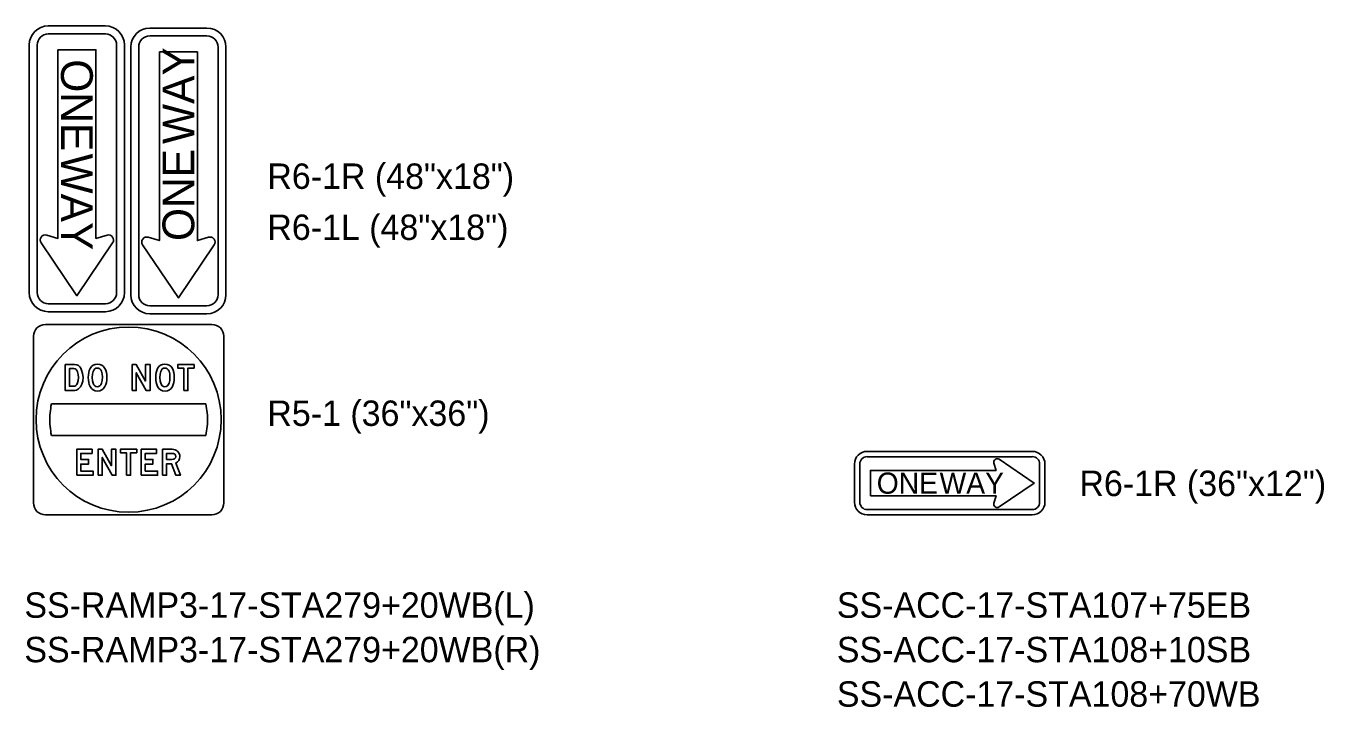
# Model space of a CAD drawing. Extents: x 620856.8 to 620948.6, y 415598.8 to 415658.2.
# Drawn here: x 620925.25 to 620945.7, y 415616.01 to 415626.74 of the extents above; entities that cross this region are included whole.
import ezdxf

# ---------------------------------------------------------------- set-up
doc = ezdxf.new("R2010")
doc.units = 0
doc.layers.add('SIGNS', color=7, linetype='Continuous')

msp = doc.modelspace()

# ---------------------------------------------------------------- linework, layer by layer
at = {"layer": 'SIGNS'}
for p, q in [((620925.604, 415626.741), (620926.504, 415626.741)), ((620927.203, 415626.708), (620928.103, 415626.708)), ((620925.304, 415622.541), (620925.304, 415626.441)), ((620926.903, 415622.508), (620926.903, 415626.408)), ((620926.504, 415622.241), (620925.604, 415622.241)), ((620928.103, 415622.208), (620927.203, 415622.208)), ((620928.182, 415622.041), (620925.557, 415622.041)), ((620928.182, 415622.041), (620925.557, 415622.041)), ((620925.369, 415621.853), (620925.369, 415619.228)), ((620925.369, 415621.853), (620925.369, 415619.228)), ((620928.369, 415619.228), (620928.369, 415621.853)), ((620928.369, 415619.228), (620928.369, 415621.853)), ((620925.641, 415620.718), (620925.636, 415620.683)), ((620925.646, 415620.754), (620925.641, 415620.718)), ((620925.653, 415620.789), (620925.646, 415620.754)), ((620928.085, 415620.789), (620925.653, 415620.789)), ((620928.092, 415620.754), (620928.085, 415620.789)), ((620928.098, 415620.718), (620928.092, 415620.754)), ((620928.103, 415620.683), (620928.098, 415620.718)), ((620925.629, 415620.576), (620925.628, 415620.541)), ((620925.628, 415620.541), (620925.629, 415620.505)), ((620925.63, 415620.612), (620925.629, 415620.576)), ((620925.632, 415620.647), (620925.63, 415620.612)), ((620925.636, 415620.683), (620925.632, 415620.647)), ((620928.106, 415620.647), (620928.103, 415620.683)), ((620928.109, 415620.612), (620928.106, 415620.647)), ((620928.11, 415620.576), (620928.109, 415620.612)), ((620928.11, 415620.54), (620928.11, 415620.576)), ((620928.11, 415620.505), (620928.11, 415620.54)), ((620925.629, 415620.505), (620925.63, 415620.469)), ((620925.63, 415620.469), (620925.632, 415620.434)), ((620925.632, 415620.434), (620925.636, 415620.398)), ((620925.636, 415620.398), (620925.641, 415620.363)), ((620925.641, 415620.363), (620925.646, 415620.327)), ((620925.646, 415620.327), (620925.653, 415620.293)), ((620928.085, 415620.293), (620928.092, 415620.327)), ((620928.092, 415620.327), (620928.098, 415620.363)), ((620928.098, 415620.363), (620928.103, 415620.398)), ((620928.103, 415620.398), (620928.106, 415620.434)), ((620928.106, 415620.434), (620928.109, 415620.469)), ((620928.109, 415620.469), (620928.11, 415620.505)), ((620925.653, 415620.293), (620928.085, 415620.293)), ((620938.304, 415619.241), (620938.304, 415619.841)), ((620941.304, 415619.841), (620941.304, 415619.241)), ((620925.557, 415619.041), (620928.182, 415619.041)), ((620925.557, 415619.041), (620928.182, 415619.041)), ((620941.104, 415619.041), (620938.504, 415619.041))]:
    msp.add_line(p, q, dxfattribs=at)
for points in [[(620926.504, 415626.616), (620925.604, 415626.616)], [(620928.103, 415626.583), (620927.203, 415626.583)], [(620925.429, 415626.441), (620925.429, 415622.541)], [(620925.579, 415623.446), (620925.754, 415623.394), (620925.754, 415626.366)], [(620925.754, 415626.366), (620926.354, 415626.366), (620926.354, 415623.394), (620926.529, 415623.446)], [(620926.679, 415622.541), (620926.679, 415626.441)], [(620926.804, 415626.441), (620926.804, 415624.491), (620926.804, 415622.541)], [(620927.028, 415626.408), (620927.028, 415622.508)], [(620927.178, 415623.413), (620927.353, 415623.362), (620927.353, 415626.333)], [(620927.353, 415626.333), (620927.953, 415626.333), (620927.953, 415623.362), (620928.129, 415623.413)], [(620928.278, 415622.508), (620928.278, 415626.408)], [(620928.403, 415626.408), (620928.403, 415624.458), (620928.403, 415622.508)], [(620926.617, 415623.325), (620926.054, 415622.491), (620925.49, 415623.325)], [(620928.217, 415623.293), (620927.653, 415622.458), (620927.09, 415623.293)], [(620925.604, 415622.366), (620926.504, 415622.366)], [(620927.203, 415622.333), (620928.103, 415622.333)], [(620926.014, 415621.408), (620925.871, 415621.408), (620925.871, 415620.999), (620926.021, 415620.999), (620926.048, 415621.005), (620926.078, 415621.024), (620926.11, 415621.057), (620926.132, 415621.099), (620926.146, 415621.149), (620926.151, 415621.209), (620926.145, 415621.266), (620926.129, 415621.321), (620926.115, 415621.35), (620926.098, 415621.373), (620926.078, 415621.391), (620926.055, 415621.402), (620926.014, 415621.408)], [(620926.001, 415621.066), (620925.935, 415621.066), (620925.935, 415621.346), (620926.007, 415621.346), (620926.025, 415621.343), (620926.041, 415621.333), (620926.055, 415621.317), (620926.065, 415621.294), (620926.076, 415621.253), (620926.079, 415621.206), (620926.075, 415621.159), (620926.064, 415621.118), (620926.052, 415621.095), (620926.038, 415621.079), (620926.021, 415621.069), (620926.001, 415621.066)], [(620926.526, 415621.204), (620926.524, 415621.246), (620926.518, 415621.284), (620926.509, 415621.318), (620926.496, 415621.347), (620926.475, 415621.377), (620926.448, 415621.398), (620926.415, 415621.411), (620926.377, 415621.416), (620926.34, 415621.411), (620926.309, 415621.398), (620926.283, 415621.376), (620926.262, 415621.346), (620926.249, 415621.316), (620926.24, 415621.284), (620926.235, 415621.247), (620926.233, 415621.206), (620926.235, 415621.164), (620926.24, 415621.126), (620926.249, 415621.093), (620926.262, 415621.063), (620926.283, 415621.032), (620926.31, 415621.009), (620926.342, 415620.996), (620926.38, 415620.991), (620926.417, 415620.995), (620926.448, 415621.009), (620926.475, 415621.031), (620926.496, 415621.062), (620926.509, 415621.092), (620926.518, 415621.126), (620926.524, 415621.163), (620926.526, 415621.204)], [(620926.458, 415621.208), (620926.454, 415621.156), (620926.443, 415621.113), (620926.431, 415621.089), (620926.416, 415621.072), (620926.397, 415621.061), (620926.375, 415621.058), (620926.354, 415621.061), (620926.337, 415621.072), (620926.322, 415621.089), (620926.311, 415621.113), (620926.301, 415621.154), (620926.297, 415621.205), (620926.301, 415621.255), (620926.311, 415621.297), (620926.322, 415621.321), (620926.336, 415621.339), (620926.353, 415621.349), (620926.374, 415621.353), (620926.396, 415621.35), (620926.415, 415621.34), (620926.43, 415621.324), (620926.443, 415621.302), (620926.454, 415621.26), (620926.458, 415621.208)], [(620927.589, 415621.204), (620927.587, 415621.246), (620927.581, 415621.284), (620927.572, 415621.318), (620927.559, 415621.347), (620927.537, 415621.377), (620927.51, 415621.398), (620927.478, 415621.411), (620927.44, 415621.416), (620927.403, 415621.411), (620927.372, 415621.398), (620927.346, 415621.376), (620927.325, 415621.346), (620927.312, 415621.316), (620927.303, 415621.284), (620927.298, 415621.247), (620927.296, 415621.206), (620927.298, 415621.164), (620927.303, 415621.126), (620927.312, 415621.093), (620927.325, 415621.063), (620927.346, 415621.032), (620927.373, 415621.009), (620927.405, 415620.996), (620927.443, 415620.991), (620927.48, 415620.995), (620927.511, 415621.009), (620927.538, 415621.031), (620927.559, 415621.062), (620927.572, 415621.092), (620927.581, 415621.126), (620927.587, 415621.163), (620927.589, 415621.204)], [(620927.52, 415621.208), (620927.517, 415621.156), (620927.506, 415621.113), (620927.494, 415621.089), (620927.479, 415621.072), (620927.46, 415621.061), (620927.438, 415621.058), (620927.417, 415621.061), (620927.4, 415621.072), (620927.385, 415621.089), (620927.374, 415621.113), (620927.364, 415621.154), (620927.36, 415621.205), (620927.364, 415621.255), (620927.374, 415621.297), (620927.385, 415621.321), (620927.399, 415621.339), (620927.416, 415621.349), (620927.436, 415621.353), (620927.459, 415621.35), (620927.478, 415621.34), (620927.493, 415621.324), (620927.506, 415621.302), (620927.517, 415621.26), (620927.52, 415621.208)], [(620927.404, 415619.666), (620927.468, 415619.666), (620927.468, 415619.845), (620927.547, 415619.845), (620927.613, 415619.666), (620927.685, 415619.666), (620927.612, 415619.856), (620927.638, 415619.874), (620927.658, 415619.899), (620927.672, 415619.928), (620927.676, 415619.959), (620927.674, 415619.983), (620927.667, 415620.005), (620927.656, 415620.025), (620927.64, 415620.042), (620927.621, 415620.056), (620927.601, 415620.066), (620927.578, 415620.072), (620927.553, 415620.074), (620927.404, 415620.074), (620927.404, 415619.666)], [(620927.468, 415619.914), (620927.468, 415620.01), (620927.554, 415620.01), (620927.576, 415620.007), (620927.595, 415619.997), (620927.608, 415619.982), (620927.613, 415619.962), (620927.608, 415619.941), (620927.593, 415619.925), (620927.574, 415619.916), (620927.55, 415619.914), (620927.468, 415619.914)], [(620938.504, 415620.041), (620939.804, 415620.041), (620941.104, 415620.041)], [(620941.104, 415619.957), (620938.504, 415619.957)], [(620940.581, 415619.916), (620941.137, 415619.541), (620940.581, 415619.165)], [(620938.387, 415619.841), (620938.387, 415619.241)], [(620938.554, 415619.341), (620938.554, 415619.741), (620940.535, 415619.741), (620940.501, 415619.857)], [(620941.221, 415619.241), (620941.221, 415619.841)], [(620940.501, 415619.224), (620940.535, 415619.341), (620938.554, 415619.341)], [(620938.504, 415619.124), (620941.104, 415619.124)]]:
    msp.add_lwpolyline(points, dxfattribs=at)
for points in [[(620926.926, 415620.999), (620926.99, 415620.999), (620926.99, 415621.278), (620927.148, 415620.999), (620927.206, 415620.999), (620927.206, 415621.408), (620927.134, 415621.408), (620927.134, 415621.148), (620926.99, 415621.408), (620926.926, 415621.408)], [(620927.737, 415620.999), (620927.802, 415620.999), (620927.802, 415621.353), (620927.899, 415621.353), (620927.899, 415621.408), (620927.643, 415621.408), (620927.643, 415621.353), (620927.737, 415621.353)], [(620926.052, 415619.666), (620926.308, 415619.666), (620926.308, 415619.73), (620926.116, 415619.73), (620926.116, 415619.842), (620926.237, 415619.842), (620926.237, 415619.914), (620926.116, 415619.914), (620926.116, 415620.01), (620926.294, 415620.01), (620926.294, 415620.074), (620926.052, 415620.074)], [(620926.389, 415619.666), (620926.453, 415619.666), (620926.453, 415619.945), (620926.611, 415619.666), (620926.669, 415619.666), (620926.669, 415620.074), (620926.597, 415620.074), (620926.597, 415619.814), (620926.453, 415620.074), (620926.389, 415620.074)], [(620926.835, 415619.666), (620926.9, 415619.666), (620926.9, 415620.02), (620926.996, 415620.02), (620926.996, 415620.074), (620926.741, 415620.074), (620926.741, 415620.02), (620926.835, 415620.02)], [(620927.068, 415619.666), (620927.324, 415619.666), (620927.324, 415619.73), (620927.131, 415619.73), (620927.131, 415619.842), (620927.253, 415619.842), (620927.253, 415619.914), (620927.131, 415619.914), (620927.131, 415620.01), (620927.31, 415620.01), (620927.31, 415620.074), (620927.068, 415620.074)]]:
    msp.add_lwpolyline(points, close=True, dxfattribs=at)
msp.add_circle((620926.869, 415620.541), 1.458, dxfattribs=at)
for centre, radius, start, end in [((620925.604, 415626.441), 0.3, 90, 180), ((620926.504, 415626.441), 0.3, 360, 90), ((620927.203, 415626.408), 0.3, 90, 180), ((620928.103, 415626.408), 0.3, 360, 90), ((620925.604, 415626.441), 0.175, 90, 180), ((620926.504, 415626.441), 0.175, 360, 90), ((620927.203, 415626.408), 0.175, 90, 180), ((620928.103, 415626.408), 0.175, 360, 90), ((620925.555, 415623.37), 0.0788, 72.3821, 215.2267), ((620926.553, 415623.37), 0.0788, 324.7733, 107.6179), ((620927.154, 415623.338), 0.0788, 72.3821, 215.2267), ((620928.152, 415623.338), 0.0788, 324.7733, 107.6179), ((620925.604, 415622.541), 0.3, 180, 270), ((620925.604, 415622.541), 0.175, 180, 270), ((620926.504, 415622.541), 0.3, 270, 360), ((620926.504, 415622.541), 0.175, 270, 360), ((620927.203, 415622.508), 0.3, 180, 270), ((620927.203, 415622.508), 0.175, 180, 270), ((620928.103, 415622.508), 0.3, 270, 360), ((620928.103, 415622.508), 0.175, 270, 360), ((620925.557, 415621.853), 0.187, 90.0002, 179.9998), ((620925.557, 415621.853), 0.187, 90.0002, 179.9998), ((620925.557, 415621.853), 0.187, 90.0002, 179.9998), ((620928.182, 415621.853), 0.187, 360, 90.0002), ((620928.182, 415621.853), 0.187, 360, 90.0002), ((620938.504, 415619.841), 0.2, 90, 180), ((620938.504, 415619.841), 0.117, 90, 180), ((620940.551, 415619.873), 0.0525, 54.7733, 197.6179), ((620941.104, 415619.841), 0.2, 360, 90), ((620941.104, 415619.841), 0.117, 360, 90), ((620925.557, 415619.228), 0.187, 179.9998, 270.0001), ((620925.557, 415619.228), 0.187, 179.9998, 270.0001), ((620928.182, 415619.228), 0.187, 270.0001, 0.0003), ((620928.182, 415619.228), 0.187, 270.0001, 0.0003), ((620938.504, 415619.241), 0.2, 180, 270), ((620938.504, 415619.241), 0.117, 180, 270), ((620940.551, 415619.208), 0.0525, 162.3821, 305.2267), ((620941.104, 415619.241), 0.2, 270, 360), ((620941.104, 415619.241), 0.117, 270, 360)]:
    msp.add_arc(centre, radius, start, end, dxfattribs=at)

# ---------------------------------------------------------------- texts
for s, height, rotation, p in [('WAY', 0.5, 90, (620927.903, 415624.882)), ('ONE', 0.5, 270, (620925.804, 415626.216)), ('WAY', 0.5, 270, (620925.804, 415624.731)), ('ONE', 0.5, 90, (620927.903, 415623.354)), ('R6-1R (48"x18")', 0.4, 0, (620929.054, 415624.175)), ('R6-1L (48"x18")', 0.4, 0, (620929.054, 415623.371)), ('R5-1 (36"x36")', 0.4, 0, (620929.054, 415620.442)), ('ONE', 0.3333, 360, (620938.654, 415619.374)), ('WAY', 0.3333, 360, (620939.644, 415619.374)), ('R6-1R (36"x12")', 0.4, 0, (620941.847, 415619.337)), ('SS-RAMP3-17-STA279+20WB(L)', 0.4, 0, (620925.227, 415617.42)), ('SS-ACC-17-STA107+75EB', 0.4, 0, (620938.026, 415617.42)), ('SS-RAMP3-17-STA279+20WB(R)', 0.4, 0, (620925.227, 415616.72)), ('SS-ACC-17-STA108+10SB', 0.4, 0, (620938.026, 415616.72)), ('SS-ACC-17-STA108+70WB', 0.4, 0, (620938.026, 415616.02))]:
    msp.add_text(s, height=height, rotation=rotation, dxfattribs=at).set_placement(p)

doc.saveas('drawing.dxf')
